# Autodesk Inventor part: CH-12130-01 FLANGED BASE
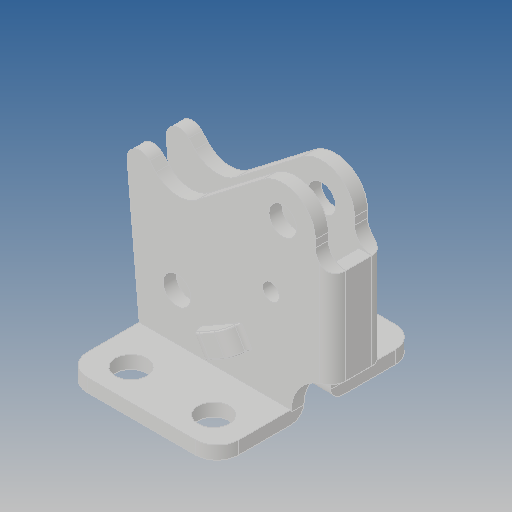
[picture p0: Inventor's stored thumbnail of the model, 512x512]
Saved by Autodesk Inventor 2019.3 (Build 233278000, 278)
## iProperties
Created: 2017-11
Part Number: CH-12130-01 FLANGED BASE
Material: Ogólny
Document SubType Name: Modeling
Designer: Admin
Density: 1 g/cm^3
Appearance: Domyślna
Author: Admin
Revision Number: ÈÎºÎ
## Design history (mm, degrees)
feature "Ô²½Ç11"
node "Bryła1"
